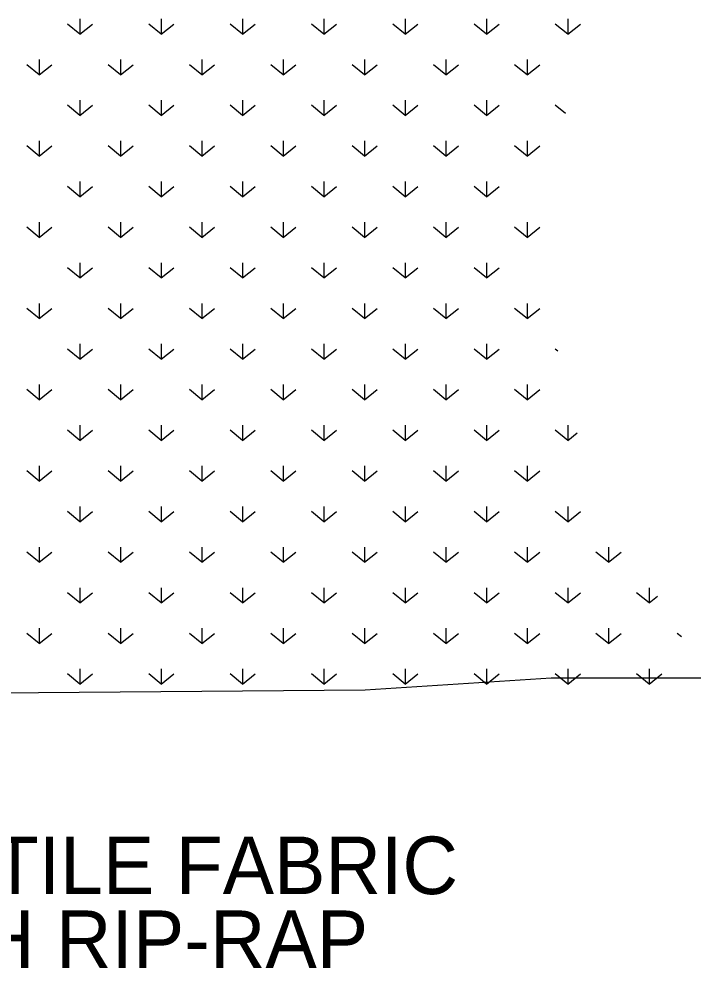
# Model space of a CAD drawing. Extents: x 10048.1 to 10113.8, y 9930.9 to 10007.5.
# Drawn here: x 10094.98 to 10107.35, y 9972.6 to 9989.83 of the extents above; entities that cross this region are included whole.
import ezdxf

# ---------------------------------------------------------------- set-up
doc = ezdxf.new("R2010")
doc.units = 0
for name, color, linetype in [('G-ANNO-TEXT', 7, 'Continuous'), ('G-DETL-OTLN', 7, 'Continuous'), ('G-DETL-PATT', 7, 'Continuous')]:
    doc.layers.add(name, color=color, linetype=linetype)

msp = doc.modelspace()

# ---------------------------------------------------------------- linework, layer by layer
at = {"layer": 'G-DETL-OTLN'}
for p, q in [((10101.261, 9977.648), (10104.634, 9977.869)), ((10104.634, 9977.869), (10107.349, 9977.869)), ((10086.798, 9977.537), (10101.261, 9977.648))]:
    msp.add_line(p, q, dxfattribs=at)
at = {"layer": 'G-DETL-PATT'}
for p, q in [((10096.087, 9989.825), (10096.087, 9989.549)), ((10097.562, 9989.825), (10097.562, 9989.549)), ((10099.036, 9989.825), (10099.036, 9989.549)), ((10100.511, 9989.825), (10100.511, 9989.549)), ((10101.986, 9989.825), (10101.986, 9989.549)), ((10103.46, 9989.825), (10103.46, 9989.549)), ((10104.935, 9989.825), (10104.935, 9989.549)), ((10096.087, 9989.549), (10095.86, 9989.733)), ((10096.087, 9989.549), (10096.315, 9989.733)), ((10097.562, 9989.549), (10097.335, 9989.733)), ((10097.562, 9989.549), (10097.789, 9989.733)), ((10099.036, 9989.549), (10098.809, 9989.733)), ((10099.036, 9989.549), (10099.264, 9989.733)), ((10100.511, 9989.549), (10100.284, 9989.733)), ((10100.511, 9989.549), (10100.738, 9989.733)), ((10101.986, 9989.549), (10101.758, 9989.733)), ((10101.986, 9989.549), (10102.213, 9989.733)), ((10103.46, 9989.549), (10103.233, 9989.733)), ((10103.46, 9989.549), (10103.687, 9989.733)), ((10104.935, 9989.549), (10104.707, 9989.733)), ((10104.935, 9989.549), (10105.162, 9989.733)), ((10095.35, 9988.811), (10095.123, 9988.996)), ((10095.35, 9989.088), (10095.35, 9988.811)), ((10095.35, 9988.811), (10095.577, 9988.996)), ((10096.825, 9988.811), (10096.597, 9988.996)), ((10096.825, 9989.088), (10096.825, 9988.811)), ((10096.825, 9988.811), (10097.052, 9988.996)), ((10098.299, 9988.811), (10098.072, 9988.996)), ((10098.299, 9989.088), (10098.299, 9988.811)), ((10098.299, 9988.811), (10098.526, 9988.996)), ((10099.774, 9988.811), (10099.546, 9988.996)), ((10099.774, 9989.088), (10099.774, 9988.811)), ((10099.774, 9988.811), (10100.001, 9988.996)), ((10101.248, 9988.811), (10101.021, 9988.996)), ((10101.248, 9989.088), (10101.248, 9988.811)), ((10101.248, 9988.811), (10101.476, 9988.996)), ((10102.723, 9988.811), (10102.496, 9988.996)), ((10102.723, 9989.088), (10102.723, 9988.811)), ((10102.723, 9988.811), (10102.95, 9988.996)), ((10104.197, 9988.811), (10103.97, 9988.996)), ((10104.197, 9989.088), (10104.197, 9988.811)), ((10104.197, 9988.811), (10104.425, 9988.996)), ((10096.087, 9988.074), (10095.86, 9988.259)), ((10096.087, 9988.351), (10096.087, 9988.074)), ((10096.087, 9988.074), (10096.315, 9988.259)), ((10097.562, 9988.074), (10097.335, 9988.259)), ((10097.562, 9988.351), (10097.562, 9988.074)), ((10097.562, 9988.074), (10097.789, 9988.259)), ((10099.036, 9988.074), (10098.809, 9988.259)), ((10099.036, 9988.351), (10099.036, 9988.074)), ((10099.036, 9988.074), (10099.264, 9988.259)), ((10100.511, 9988.074), (10100.284, 9988.259)), ((10100.511, 9988.351), (10100.511, 9988.074)), ((10100.511, 9988.074), (10100.738, 9988.259)), ((10101.986, 9988.074), (10101.758, 9988.259)), ((10101.986, 9988.351), (10101.986, 9988.074)), ((10101.986, 9988.074), (10102.213, 9988.259)), ((10103.46, 9988.074), (10103.233, 9988.259)), ((10103.46, 9988.351), (10103.46, 9988.074)), ((10103.46, 9988.074), (10103.687, 9988.259)), ((10104.892, 9988.111), (10104.707, 9988.259)), ((10095.35, 9987.613), (10095.35, 9987.337)), ((10096.825, 9987.613), (10096.825, 9987.337)), ((10098.299, 9987.613), (10098.299, 9987.337)), ((10099.774, 9987.613), (10099.774, 9987.337)), ((10101.248, 9987.613), (10101.248, 9987.337)), ((10102.723, 9987.613), (10102.723, 9987.337)), ((10104.197, 9987.613), (10104.197, 9987.337)), ((10095.35, 9987.337), (10095.123, 9987.521)), ((10095.35, 9987.337), (10095.577, 9987.521)), ((10096.825, 9987.337), (10096.597, 9987.521)), ((10096.825, 9987.337), (10097.052, 9987.521)), ((10098.299, 9987.337), (10098.072, 9987.521)), ((10098.299, 9987.337), (10098.526, 9987.521)), ((10099.774, 9987.337), (10099.546, 9987.521)), ((10099.774, 9987.337), (10100.001, 9987.521)), ((10101.248, 9987.337), (10101.021, 9987.521)), ((10101.248, 9987.337), (10101.476, 9987.521)), ((10102.723, 9987.337), (10102.496, 9987.521)), ((10102.723, 9987.337), (10102.95, 9987.521)), ((10104.197, 9987.337), (10103.97, 9987.521)), ((10104.197, 9987.337), (10104.425, 9987.521)), ((10096.087, 9986.876), (10096.087, 9986.6)), ((10097.562, 9986.876), (10097.562, 9986.6)), ((10099.036, 9986.876), (10099.036, 9986.6)), ((10100.511, 9986.876), (10100.511, 9986.6)), ((10101.986, 9986.876), (10101.986, 9986.6)), ((10103.46, 9986.876), (10103.46, 9986.6)), ((10096.087, 9986.6), (10095.86, 9986.784)), ((10096.087, 9986.6), (10096.315, 9986.784)), ((10097.562, 9986.6), (10097.335, 9986.784)), ((10097.562, 9986.6), (10097.789, 9986.784)), ((10099.036, 9986.6), (10098.809, 9986.784)), ((10099.036, 9986.6), (10099.264, 9986.784)), ((10100.511, 9986.6), (10100.284, 9986.784)), ((10100.511, 9986.6), (10100.738, 9986.784)), ((10101.986, 9986.6), (10101.758, 9986.784)), ((10101.986, 9986.6), (10102.213, 9986.784)), ((10103.46, 9986.6), (10103.233, 9986.784)), ((10103.46, 9986.6), (10103.687, 9986.784)), ((10095.35, 9985.862), (10095.123, 9986.047)), ((10095.35, 9986.139), (10095.35, 9985.862)), ((10095.35, 9985.862), (10095.577, 9986.047)), ((10096.825, 9985.862), (10096.597, 9986.047)), ((10096.825, 9986.139), (10096.825, 9985.862)), ((10096.825, 9985.862), (10097.052, 9986.047)), ((10098.299, 9985.862), (10098.072, 9986.047)), ((10098.299, 9986.139), (10098.299, 9985.862)), ((10098.299, 9985.862), (10098.526, 9986.047)), ((10099.774, 9985.862), (10099.546, 9986.047)), ((10099.774, 9986.139), (10099.774, 9985.862)), ((10099.774, 9985.862), (10100.001, 9986.047)), ((10101.248, 9985.862), (10101.021, 9986.047)), ((10101.248, 9986.139), (10101.248, 9985.862)), ((10101.248, 9985.862), (10101.476, 9986.047)), ((10102.723, 9985.862), (10102.496, 9986.047)), ((10102.723, 9986.139), (10102.723, 9985.862)), ((10102.723, 9985.862), (10102.95, 9986.047)), ((10104.197, 9985.862), (10103.97, 9986.047)), ((10104.197, 9986.139), (10104.197, 9985.862)), ((10104.197, 9985.862), (10104.425, 9986.047)), ((10096.087, 9985.402), (10096.087, 9985.125)), ((10097.562, 9985.402), (10097.562, 9985.125)), ((10099.036, 9985.402), (10099.036, 9985.125)), ((10100.511, 9985.402), (10100.511, 9985.125)), ((10101.986, 9985.402), (10101.986, 9985.125)), ((10103.46, 9985.402), (10103.46, 9985.125)), ((10096.087, 9985.125), (10095.86, 9985.309)), ((10096.087, 9985.125), (10096.315, 9985.309)), ((10097.562, 9985.125), (10097.335, 9985.309)), ((10097.562, 9985.125), (10097.789, 9985.309)), ((10099.036, 9985.125), (10098.809, 9985.309)), ((10099.036, 9985.125), (10099.264, 9985.309)), ((10100.511, 9985.125), (10100.284, 9985.309)), ((10100.511, 9985.125), (10100.738, 9985.309)), ((10101.986, 9985.125), (10101.758, 9985.309)), ((10101.986, 9985.125), (10102.213, 9985.309)), ((10103.46, 9985.125), (10103.233, 9985.309)), ((10103.46, 9985.125), (10103.687, 9985.309)), ((10095.35, 9984.664), (10095.35, 9984.388)), ((10096.825, 9984.664), (10096.825, 9984.388)), ((10098.299, 9984.664), (10098.299, 9984.388)), ((10099.774, 9984.664), (10099.774, 9984.388)), ((10101.248, 9984.664), (10101.248, 9984.388)), ((10102.723, 9984.664), (10102.723, 9984.388)), ((10104.197, 9984.664), (10104.197, 9984.388)), ((10095.35, 9984.388), (10095.123, 9984.572)), ((10095.35, 9984.388), (10095.577, 9984.572)), ((10096.825, 9984.388), (10096.597, 9984.572)), ((10096.825, 9984.388), (10097.052, 9984.572)), ((10098.299, 9984.388), (10098.072, 9984.572)), ((10098.299, 9984.388), (10098.526, 9984.572)), ((10099.774, 9984.388), (10099.546, 9984.572)), ((10099.774, 9984.388), (10100.001, 9984.572)), ((10101.248, 9984.388), (10101.021, 9984.572)), ((10101.248, 9984.388), (10101.476, 9984.572)), ((10102.723, 9984.388), (10102.496, 9984.572)), ((10102.723, 9984.388), (10102.95, 9984.572)), ((10104.197, 9984.388), (10103.97, 9984.572)), ((10104.197, 9984.388), (10104.425, 9984.572)), ((10096.087, 9983.651), (10095.86, 9983.835)), ((10096.087, 9983.927), (10096.087, 9983.651)), ((10096.087, 9983.651), (10096.315, 9983.835)), ((10097.562, 9983.651), (10097.335, 9983.835)), ((10097.562, 9983.927), (10097.562, 9983.651)), ((10097.562, 9983.651), (10097.789, 9983.835)), ((10099.036, 9983.651), (10098.809, 9983.835)), ((10099.036, 9983.927), (10099.036, 9983.651)), ((10099.036, 9983.651), (10099.264, 9983.835)), ((10100.511, 9983.651), (10100.284, 9983.835)), ((10100.511, 9983.927), (10100.511, 9983.651)), ((10100.511, 9983.651), (10100.738, 9983.835)), ((10101.986, 9983.651), (10101.758, 9983.835)), ((10101.986, 9983.927), (10101.986, 9983.651)), ((10101.986, 9983.651), (10102.213, 9983.835)), ((10103.46, 9983.651), (10103.233, 9983.835)), ((10103.46, 9983.927), (10103.46, 9983.651)), ((10103.46, 9983.651), (10103.687, 9983.835)), ((10104.75, 9983.798), (10104.707, 9983.835)), ((10095.35, 9982.913), (10095.123, 9983.098)), ((10095.35, 9983.19), (10095.35, 9982.913)), ((10095.35, 9982.913), (10095.577, 9983.098)), ((10096.825, 9982.913), (10096.597, 9983.098)), ((10096.825, 9983.19), (10096.825, 9982.913)), ((10096.825, 9982.913), (10097.052, 9983.098)), ((10098.299, 9982.913), (10098.072, 9983.098)), ((10098.299, 9983.19), (10098.299, 9982.913)), ((10098.299, 9982.913), (10098.526, 9983.098)), ((10099.774, 9982.913), (10099.546, 9983.098)), ((10099.774, 9983.19), (10099.774, 9982.913)), ((10099.774, 9982.913), (10100.001, 9983.098)), ((10101.248, 9982.913), (10101.021, 9983.098)), ((10101.248, 9983.19), (10101.248, 9982.913)), ((10101.248, 9982.913), (10101.476, 9983.098)), ((10102.723, 9982.913), (10102.496, 9983.098)), ((10102.723, 9983.19), (10102.723, 9982.913)), ((10102.723, 9982.913), (10102.95, 9983.098)), ((10104.197, 9982.913), (10103.97, 9983.098)), ((10104.197, 9983.19), (10104.197, 9982.913)), ((10104.197, 9982.913), (10104.425, 9983.098)), ((10096.087, 9982.452), (10096.087, 9982.176)), ((10097.562, 9982.452), (10097.562, 9982.176)), ((10099.036, 9982.452), (10099.036, 9982.176)), ((10100.511, 9982.452), (10100.511, 9982.176)), ((10101.986, 9982.452), (10101.986, 9982.176)), ((10103.46, 9982.452), (10103.46, 9982.176)), ((10104.935, 9982.452), (10104.935, 9982.176)), ((10096.087, 9982.176), (10095.86, 9982.36)), ((10096.087, 9982.176), (10096.315, 9982.36)), ((10097.562, 9982.176), (10097.335, 9982.36)), ((10097.562, 9982.176), (10097.789, 9982.36)), ((10099.036, 9982.176), (10098.809, 9982.36)), ((10099.036, 9982.176), (10099.264, 9982.36)), ((10100.511, 9982.176), (10100.284, 9982.36)), ((10100.511, 9982.176), (10100.738, 9982.36)), ((10101.986, 9982.176), (10101.758, 9982.36)), ((10101.986, 9982.176), (10102.213, 9982.36)), ((10103.46, 9982.176), (10103.233, 9982.36)), ((10103.46, 9982.176), (10103.687, 9982.36)), ((10104.935, 9982.176), (10104.707, 9982.36)), ((10104.935, 9982.176), (10105.101, 9982.311)), ((10095.35, 9981.715), (10095.35, 9981.439)), ((10096.825, 9981.715), (10096.825, 9981.439)), ((10098.299, 9981.715), (10098.299, 9981.439)), ((10099.774, 9981.715), (10099.774, 9981.439)), ((10101.248, 9981.715), (10101.248, 9981.439)), ((10102.723, 9981.715), (10102.723, 9981.439)), ((10104.197, 9981.715), (10104.197, 9981.439)), ((10095.35, 9981.439), (10095.123, 9981.623)), ((10095.35, 9981.439), (10095.577, 9981.623)), ((10096.825, 9981.439), (10096.597, 9981.623)), ((10096.825, 9981.439), (10097.052, 9981.623)), ((10098.299, 9981.439), (10098.072, 9981.623)), ((10098.299, 9981.439), (10098.526, 9981.623)), ((10099.774, 9981.439), (10099.546, 9981.623)), ((10099.774, 9981.439), (10100.001, 9981.623)), ((10101.248, 9981.439), (10101.021, 9981.623)), ((10101.248, 9981.439), (10101.476, 9981.623)), ((10102.723, 9981.439), (10102.496, 9981.623)), ((10102.723, 9981.439), (10102.95, 9981.623)), ((10104.197, 9981.439), (10103.97, 9981.623)), ((10104.197, 9981.439), (10104.425, 9981.623)), ((10096.087, 9980.701), (10095.86, 9980.886)), ((10096.087, 9980.978), (10096.087, 9980.701)), ((10096.087, 9980.701), (10096.315, 9980.886)), ((10097.562, 9980.701), (10097.335, 9980.886)), ((10097.562, 9980.978), (10097.562, 9980.701)), ((10097.562, 9980.701), (10097.789, 9980.886)), ((10099.036, 9980.701), (10098.809, 9980.886)), ((10099.036, 9980.978), (10099.036, 9980.701)), ((10099.036, 9980.701), (10099.264, 9980.886)), ((10100.511, 9980.701), (10100.284, 9980.886)), ((10100.511, 9980.978), (10100.511, 9980.701)), ((10100.511, 9980.701), (10100.738, 9980.886)), ((10101.986, 9980.701), (10101.758, 9980.886)), ((10101.986, 9980.978), (10101.986, 9980.701)), ((10101.986, 9980.701), (10102.213, 9980.886)), ((10103.46, 9980.701), (10103.233, 9980.886)), ((10103.46, 9980.978), (10103.46, 9980.701)), ((10103.46, 9980.701), (10103.687, 9980.886)), ((10104.935, 9980.701), (10104.707, 9980.886)), ((10104.935, 9980.978), (10104.935, 9980.701)), ((10104.935, 9980.701), (10105.162, 9980.886)), ((10095.35, 9980.241), (10095.35, 9979.964)), ((10096.825, 9980.241), (10096.825, 9979.964)), ((10098.299, 9980.241), (10098.299, 9979.964)), ((10099.774, 9980.241), (10099.774, 9979.964)), ((10101.248, 9980.241), (10101.248, 9979.964)), ((10102.723, 9980.241), (10102.723, 9979.964)), ((10104.197, 9980.241), (10104.197, 9979.964)), ((10105.672, 9980.241), (10105.672, 9979.964)), ((10095.35, 9979.964), (10095.123, 9980.148)), ((10095.35, 9979.964), (10095.577, 9980.148)), ((10096.825, 9979.964), (10096.597, 9980.148)), ((10096.825, 9979.964), (10097.052, 9980.148)), ((10098.299, 9979.964), (10098.072, 9980.148)), ((10098.299, 9979.964), (10098.526, 9980.148)), ((10099.774, 9979.964), (10099.546, 9980.148)), ((10099.774, 9979.964), (10100.001, 9980.148)), ((10101.248, 9979.964), (10101.021, 9980.148)), ((10101.248, 9979.964), (10101.476, 9980.148)), ((10102.723, 9979.964), (10102.496, 9980.148)), ((10102.723, 9979.964), (10102.95, 9980.148)), ((10104.197, 9979.964), (10103.97, 9980.148)), ((10104.197, 9979.964), (10104.425, 9980.148)), ((10105.672, 9979.964), (10105.445, 9980.148)), ((10105.672, 9979.964), (10105.899, 9980.148)), ((10096.087, 9979.503), (10096.087, 9979.227)), ((10097.562, 9979.503), (10097.562, 9979.227)), ((10099.036, 9979.503), (10099.036, 9979.227)), ((10100.511, 9979.503), (10100.511, 9979.227)), ((10101.986, 9979.503), (10101.986, 9979.227)), ((10103.46, 9979.503), (10103.46, 9979.227)), ((10104.935, 9979.503), (10104.935, 9979.227)), ((10106.409, 9979.503), (10106.409, 9979.227)), ((10096.087, 9979.227), (10095.86, 9979.411)), ((10096.087, 9979.227), (10096.315, 9979.411)), ((10097.562, 9979.227), (10097.335, 9979.411)), ((10097.562, 9979.227), (10097.789, 9979.411)), ((10099.036, 9979.227), (10098.809, 9979.411)), ((10099.036, 9979.227), (10099.264, 9979.411)), ((10100.511, 9979.227), (10100.284, 9979.411)), ((10100.511, 9979.227), (10100.738, 9979.411)), ((10101.986, 9979.227), (10101.758, 9979.411)), ((10101.986, 9979.227), (10102.213, 9979.411)), ((10103.46, 9979.227), (10103.233, 9979.411)), ((10103.46, 9979.227), (10103.687, 9979.411)), ((10104.935, 9979.227), (10104.707, 9979.411)), ((10104.935, 9979.227), (10105.162, 9979.411)), ((10106.409, 9979.227), (10106.182, 9979.411)), ((10106.409, 9979.227), (10106.563, 9979.35)), ((10095.35, 9978.49), (10095.123, 9978.674)), ((10095.35, 9978.766), (10095.35, 9978.49)), ((10095.35, 9978.49), (10095.577, 9978.674)), ((10096.825, 9978.49), (10096.597, 9978.674)), ((10096.825, 9978.766), (10096.825, 9978.49)), ((10096.825, 9978.49), (10097.052, 9978.674)), ((10098.299, 9978.49), (10098.072, 9978.674)), ((10098.299, 9978.766), (10098.299, 9978.49)), ((10098.299, 9978.49), (10098.526, 9978.674)), ((10099.774, 9978.49), (10099.546, 9978.674)), ((10099.774, 9978.766), (10099.774, 9978.49)), ((10099.774, 9978.49), (10100.001, 9978.674)), ((10101.248, 9978.49), (10101.021, 9978.674)), ((10101.248, 9978.766), (10101.248, 9978.49)), ((10101.248, 9978.49), (10101.476, 9978.674)), ((10102.723, 9978.49), (10102.496, 9978.674)), ((10102.723, 9978.766), (10102.723, 9978.49)), ((10102.723, 9978.49), (10102.95, 9978.674)), ((10104.197, 9978.49), (10103.97, 9978.674)), ((10104.197, 9978.766), (10104.197, 9978.49)), ((10104.197, 9978.49), (10104.425, 9978.674)), ((10105.672, 9978.49), (10105.445, 9978.674)), ((10105.672, 9978.766), (10105.672, 9978.49)), ((10105.672, 9978.49), (10105.899, 9978.674)), ((10106.993, 9978.612), (10106.919, 9978.674)), ((10096.087, 9977.752), (10095.86, 9977.937)), ((10096.087, 9978.029), (10096.087, 9977.752)), ((10096.087, 9977.752), (10096.315, 9977.937)), ((10097.562, 9977.752), (10097.335, 9977.937)), ((10097.562, 9978.029), (10097.562, 9977.752)), ((10097.562, 9977.752), (10097.789, 9977.937)), ((10099.036, 9977.752), (10098.809, 9977.937)), ((10099.036, 9978.029), (10099.036, 9977.752)), ((10099.036, 9977.752), (10099.264, 9977.937)), ((10100.511, 9977.752), (10100.284, 9977.937)), ((10100.511, 9978.029), (10100.511, 9977.752)), ((10100.511, 9977.752), (10100.738, 9977.937)), ((10101.986, 9977.752), (10101.758, 9977.937)), ((10101.986, 9978.029), (10101.986, 9977.752)), ((10101.986, 9977.752), (10102.213, 9977.937)), ((10103.46, 9977.752), (10103.233, 9977.937)), ((10103.46, 9978.029), (10103.46, 9977.752)), ((10103.46, 9977.752), (10103.687, 9977.937)), ((10104.935, 9977.752), (10104.707, 9977.937)), ((10104.935, 9978.029), (10104.935, 9977.752)), ((10104.935, 9977.752), (10105.162, 9977.937)), ((10106.409, 9977.752), (10106.182, 9977.937)), ((10106.409, 9978.029), (10106.409, 9977.752)), ((10106.409, 9977.752), (10106.637, 9977.937))]:
    msp.add_line(p, q, dxfattribs=at)

# ---------------------------------------------------------------- texts
at = {"layer": 'G-ANNO-TEXT'}
for s, p in [('GEOTEXTILE FABRIC', (10088.669, 9973.942)), ('BENEATH RIP-RAP', (10088.669, 9972.601))]:
    msp.add_text(s, height=1.044, dxfattribs=at).set_placement(p)

doc.saveas('drawing.dxf')
